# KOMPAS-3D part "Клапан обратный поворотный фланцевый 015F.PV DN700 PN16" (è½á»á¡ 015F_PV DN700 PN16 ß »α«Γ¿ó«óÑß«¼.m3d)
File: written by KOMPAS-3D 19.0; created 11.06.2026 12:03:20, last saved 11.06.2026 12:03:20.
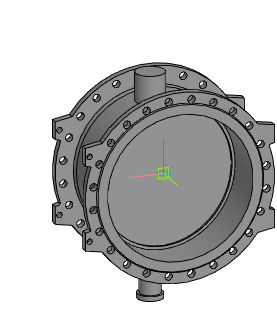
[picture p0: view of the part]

Document properties: Автор: Энергия; Полное имя файла: Z:\3.Личные\kachalov\001_3d для проектировщиков\5.5 Тип 015F.PV Клапан обратный поворотный с двумя эксцентриками\_stp_Клапан 015F.PV DN300-DN1200 с противовесом\Клапан 015F_PV DN700 PN16 с противовесом.m3d

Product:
- Part/product: Клапан обратный поворотный фланцевый 015F.PV DN700 PN16

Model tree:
1. Операция без истории:1
2. Сплайн:1
     Координата Y = 30; Координата Z = 350; Вес = 1; Координата X = 700; Координата Y = 122.157; Координата Z = 350; Вес = 0.333333; Координата X = 700; Координата Y = 122.157; Координата Z = -350; Вес = 0.333333; Координата Y = 30; Координата Z = -350; Вес = 1; Координата X = -700; Координата Y = -62.1567; Координата Z = -350; Вес = 0.333333; Координата X = -700; Координата Y = -62.1567; Координата Z = 350; Вес = 0.333333; Порядок = 4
